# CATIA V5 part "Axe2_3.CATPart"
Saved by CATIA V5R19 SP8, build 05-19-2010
Part number: Axe2_3
Publications: "Arête"
Bounding box of the stored display mesh (mm): x -10 to 10, y 113.822 to 125.822, z 112.331 to 124.331
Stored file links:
  C:\Users\thinkmotion1\Desktop\Khaled_IAO_Pack2\IAO_2010_1412_jclement\Non_Optimise\Axe2_3.CATPart
  C:\Users\thinkmotion1\Desktop\Khaled_IAO_Pack2\IAO_2010_1412_jclement\Non_Optimise\Synthese IAO_2.CATProduct
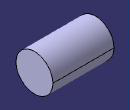
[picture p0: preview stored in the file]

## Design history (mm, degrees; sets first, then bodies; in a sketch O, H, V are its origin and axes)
Set1
  DatumCurve1: linked copy from another document
Set2
  Point1: type Center, Curve edge [start face of Pad1 | face of Pad1 from Sketch1.A1]
  Point2: type Center, Curve edge [face of Pad1 from Sketch1.A1 | end face of Pad1]
  Line1: type PtPt, FirstPoint Point1, SecondPoint Point2
  Point3: type Between, FirstPoint Point1, SecondPoint Point2, Ratio 0.5, Support Line1
Body1 (main body)
  Sketch1 on yz-plane, origin (0, 0, 0), H (0, 1, 0), V (0, 0, 1)
    circle A1 centre (119.8216, 118.3315) radius 6
    reference projected circle E1 centre (119.8216, 118.3315) radius 6 from edge of DatumCurve1
    coincidence: A1 E1
  Pad1: profile Sketch1, direction (1, 0, 0), length 10, mirrored extent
